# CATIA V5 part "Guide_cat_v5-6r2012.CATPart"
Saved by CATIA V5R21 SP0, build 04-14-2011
Part number: Guide
Bounding box of the stored display mesh (mm): x -5 to 5, y -5 to 5, z -25 to 25
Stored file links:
  D:\APS\CATIA V5-6R-2013-Project\CATIA V5-6R2013_partfiles\Tutorials\c16_catia_v5-6r2013_tut\Cam Follower mechanism\Guide_cat_v5-6r2012.CATPart
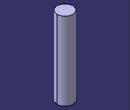
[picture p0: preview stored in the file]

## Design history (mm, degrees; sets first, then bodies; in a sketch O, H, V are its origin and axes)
Body1 (main body)
  Sketch1 on xy-plane, origin (0, 0, 0), H (1, 0, 0), V (0, 1, 0)
    circle A1 centre (0, 0) radius 5
    radius A1 = 5
  Pad1: profile Sketch1, direction (0, 0, 1), length 25, mirrored extent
